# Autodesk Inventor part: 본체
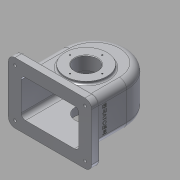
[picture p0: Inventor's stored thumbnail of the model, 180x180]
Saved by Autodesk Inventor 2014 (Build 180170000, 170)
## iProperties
Created: 2016-10
Part Number: 본체
Material: 알루미늄 6061
Document SubType Name: Modeling
Designer: SCD-A13
Density: 2.71 g/cm^3
Appearance: 알루미늄 - 평지
Mass: 1165.05 g
Surface Area: 1200.06 cm^2
Volume: 429.908 cm^3
Author: SCD-A13
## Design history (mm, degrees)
sketch "스케치1"
  geometry: L1 (-32.5, -38.5)-(32.5, -38.5); L2 (32.5, -38.5)-(32.5, 38.5); L3 (32.5, 38.5)-(-32.5, 38.5); L4 (-32.5, 38.5)-(-32.5, -38.5); L5 (-32.5, -38.5)-(32.5, 38.5); L6 (32.5, -38.5)-(-32.5, 38.5); 1 further point
  constraints: 12 end point, 2 midpoint, 2 parallel, 1 horizontal, 1 perpendicular
  dimensions: "d0" = 65 distance of L3.end L2.end; "d1" = 77 distance of L2.end L1.end
extrude "돌출1" new body sketch "스케치1" stored distance "d2" = 116; taper "d3" = 0 deg
sketch "스케치2"
  geometry: L1 (-58, 32.5)-(58, 32.5) reference; A1 r 58 centre (0, 32.5) between (58, 32.5) and (-58, 32.5); 1 further point
  constraints: 2 point on circle, 1 centre point
  dimensions: "d4" = 58 radius of A1
extrude "돌출2" join sketch "스케치2" stored distance "d5" = 77; taper "d6" = 0 deg
feature "쉘1" dims "d13" = 6
sketch "스케치13"
  geometry: L1 (32.5, -32.5)-(-32.5, -32.5) reference; L2 (-32.5, 32.5)-(32.5, 32.5) reference; L3 (-32.5, 33.5)-(32.5, 33.5); L4 (32.5, -33.5)-(-32.5, -33.5); L5 (32.5, 33.5)-(32.5, 32.5); L6 (-32.5, 33.5)-(-32.5, 32.5); L7 (-32.5, -32.5)-(-32.5, -33.5); L8 (32.5, -32.5)-(32.5, -33.5); 1 further point
  constraints: 12 end point, 3 equal length, 1 perpendicular
  dimensions: "d73" = 1 distance between parallel lines of L3 L2; "d74" = 1 distance between parallel lines of L4 L1
extrude "돌출7" cut sketch "스케치13" stored distance "d75" = 104; taper "d76" = 0 deg
sketch "스케치14"
  geometry: L1 (104, -1)-(0, -1) reference; L2 (52, -33.5)-(52, -1); L3 (104, -67)-(0, -67) reference; L4 (104, 0)-(52, 0); L5 (52, 0)-(52, -67); L6 (52, -67)-(104, -67); L7 (104, -67)-(104, 0)
  constraints: 10 end point, 2 midpoint, 2 parallel, 1 horizontal, 1 perpendicular
revolve "회전3" sketch "스케치14" stored, may be unused: angle "d77" = 180 deg
sketch "스케치3"
  geometry: L1 (0, 0)-(116, 0) reference; L2 (0, 0)-(0, 65) reference; L3 (0, 50)-(116, 50); C1 r 37.5 at (58, 50); 1 further point
  constraints: 2 end point, 1 centre point, 1 midpoint, 1 parallel
  dimensions: "d7" = 50 distance between parallel lines of L1 L3; "d8" = 75 diameter of C1; "d9" = 58 distance from line of L2 C1.centre
extrude "돌출3" join sketch "스케치3" distance "d10" = 5; taper "d11" = 0 deg
sketch "스케치4"
  geometry: L1 (-32.5, -38.5)-(-32.5, 38.5) reference; L2 (17.5, -38.5)-(17.5, 48.654); L3 (55, 43.5)-(-20, 43.5) reference; L4 (37.5, 33.5)-(37.5, 19.5); L5 (37.5, 19.5)-(45.5, 19.5); L6 (45.5, 19.5)-(57.247, 33.5); L7 (57.247, 33.5)-(37.5, 33.5); L8 (84.5, 33.5)-(32.5, 33.5) reference; 1 further point
  constraints: 10 end point, 2 perpendicular, 2 point on line, 1 parallel
  dimensions: "d12" = 50 distance between parallel lines of L1 L2; "d14" = 14 distance of L4.start L4.end; "d15" = 40 diameter of L4.end L2; "d16" = 50 deg angle of L5 L6; "d17" = 56 diameter of L5.end L2
revolve "회전1" sketch "스케치4" stored, may be unused: angle "d18" = 90 deg
sketch "스케치5"
  geometry: L1 (-32.5, -32.5)-(-32.5, 32.5) reference; L2 (17.5, 44.656)-(17.5, -39.016); L3 (37.5, 19.5)-(37.5, 33.5) reference; L4 (-2.5, 19.5)-(-2.5, 33.5) reference; L5 (55, 43.5)-(-20, 43.5) reference; L6 (32.5, -38.5)-(-32.5, -38.5) reference; L7 (37.5, 43.5)-(17.5, 43.5); L8 (17.5, 43.5)-(17.5, -38.5); L9 (17.5, -38.5)-(37.5, -38.5); L10 (37.5, -38.5)-(37.5, 43.5); 1 further point
  constraints: 10 end point, 4 point on line, 3 parallel, 1 horizontal, 1 perpendicular
  dimensions: "d78" = 50 distance between parallel lines of L1 L2
revolve "회전2" sketch "스케치5" stored, may be unused: angle "d21" = 90 deg
sketch "스케치6"
  geometry: C1 r 20 at (58, 50) reference; C2 r 31 at (58, 50); 1 further point
  constraints: 1 centre point, 1 coincident
  dimensions: "d22" = 62 diameter of C2
extrude "돌출4" join sketch "스케치6" distance "d23" = 10; taper "d24" = 0 deg
sketch "스케치7" dims "d25" = 52
  geometry: L1 (0, 0)-(0, 26); C1 r 20 at (0, 0) reference; 2 further points
  constraints: 2 coincident, 2 end point, 1 vertical, 1 vertical alignment, 2 other
hole "구멍1" sketch "스케치7" at (0, 26) diameter "d26" = 2.459; stored, may be unused: countersink angle "d30" = 90 deg, drill point angle "d32" = 118 deg; dims "d27" = 6, "d28" = 4, "d29" = 2, "d31" = 8
sketch "스케치8" dims "d33" = 58
  geometry: L1 (0, 0)-(0, 29); C1 r 37.5 at (0, 0) reference; 1 further point
  constraints: 2 end point, 1 coincident, 1 vertical, 1 vertical alignment, 2 other
hole "구멍2" sketch "스케치8" at (0, 29) diameter "d34" = 2.459; stored, may be unused: countersink angle "d38" = 90 deg, drill point angle "d40" = 118 deg; dims "d35" = 6, "d36" = 4, "d37" = 2, "d39" = 8
sketch "스케치9"
  geometry: L1 (133, -16.5)-(-17, -16.5); L2 (-17, -16.5)-(-17, 93.5); L3 (-17, 93.5)-(133, 93.5); L4 (133, 93.5)-(133, -16.5); L5 (133, -16.5)-(-17, 93.5); L6 (-17, -16.5)-(133, 93.5); L7 (6, 6)-(110, 71); L8 (110, 6)-(6, 71); L9 (6, 72)-(110, 72); L10 (110, 72)-(110, 5); L11 (110, 5)-(6, 5); L12 (6, 5)-(6, 72); 1 further point
  constraints: 24 end point, 4 midpoint, 4 parallel, 2 horizontal, 2 perpendicular
  dimensions: "d44" = 150 distance of L2.end L3.end; "d45" = 110 distance of L1.end L2.end
extrude "돌출5" join sketch "스케치9" distance "d46" = 15; taper "d47" = 0 deg
node "작업 평면1"
sketch "스케치10"
  geometry: C1 r 6 at (58, 38.5); 1 further point
  constraints: 1 centre point, 1 coincident
  dimensions: "d49" = 12 diameter of C1
extrude "돌출6" join sketch "스케치10" stored distance "d50" = 15; taper "d51" = 10 deg
sketch "스케치11"
  geometry: C1 r 6 at (0, 0) reference; 1 further point
  constraints: 1 coincident
hole "구멍3" sketch "스케치11" at (0, 0) diameter "d52" = 4.459; stored, may be unused: countersink angle "d56" = 90 deg, drill point angle "d58" = 118 deg; dims "d53" = 30, "d54" = 4, "d55" = 2, "d57" = 8
sketch "스케치12"
  geometry: L1 (121, -81.5)-(-5, -81.5); L2 (-5, -81.5)-(-5, 4.5); L3 (-5, 4.5)-(121, 4.5); L4 (121, 4.5)-(121, -81.5); L5 (121, -81.5)-(-5, 4.5); L6 (-5, -81.5)-(121, 4.5); 1 further point
  constraints: 12 end point, 2 midpoint, 2 parallel, 1 horizontal, 1 perpendicular
  dimensions: "d59" = 126 distance of L2.end L3.end; "d60" = 86 distance of L1.end L2.end
hole "구멍4" sketch "스케치12" at (-5, -81.5), (-5, 4.5), (121, 4.5), (121, -81.5) diameter "d61" = 5; stored, may be unused: countersink angle "d65" = 90 deg, drill point angle "d67" = 0 deg; dims "d62" = 30, "d63" = 12, "d64" = 5, "d66" = 8
fillet "모깎기1" dims "d68" = 12
fillet "모깎기3" dims "d70" = 13
fillet "모깎기4" dims "d79" = 8
chamfer "모따기1" distance "d80" = 1; stored, may be unused: second distance "d81" = 2, angle "d82" = 45 deg
fillet "모깎기5" dims "d83" = 3
node "작업 평면2"
sketch "스케치15"
  geometry: L1 (-47.5, -43)-(-47.5, 43) reference; L2 (32.5, 38.5)-(-29.5, 38.5) reference; 2 further points
  constraints: 1 other
  dimensions: "d85" = 38.5 distance from line of L2 point (-7.5, 0); "d86" = 40 distance from line of L1 point (-7.5, 0)
feature "엠보싱1" sketch "스케치15" dims "d0" = 65, "d1" = 77, "d7" = 50, "d8" = 75, "d9" = 58, "d87" = 0.5, "d88" = 0
node "솔리드1"
pattern_circular "원형 패턴1" dims angle "d42" = 360 deg
other parameters: "d48" = -144
